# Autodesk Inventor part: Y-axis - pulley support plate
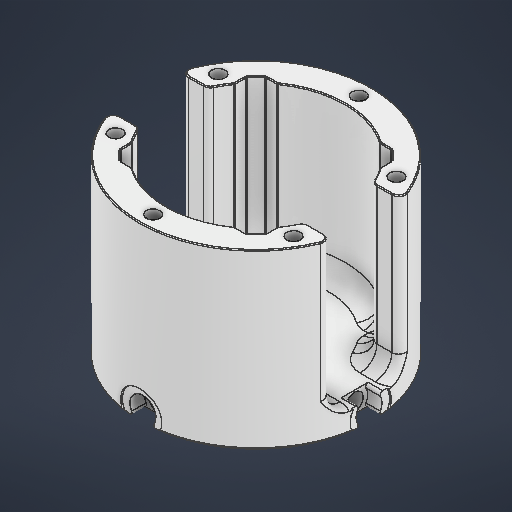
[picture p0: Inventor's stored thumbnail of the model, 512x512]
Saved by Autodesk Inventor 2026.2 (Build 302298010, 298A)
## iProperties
Created: 2026-04
Part Number: Y-axis - pulley support plate
Material: PBT 플라스틱
Document SubType Name: Modeling
Designer: work
Density: 1.31 g/cm^3
Appearance: 매끄러움 - 흰색
Author: work
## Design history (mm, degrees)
sketch "스케치1"
  geometry: L1 (-22, 22)-(22, 22); L2 (22, 22)-(22, -22); L3 (22, -22)-(-22, -22); L4 (-22, -22)-(-22, 22); L5 (-22, 22)-(22, -22); L6 (22, 22)-(-22, -22); L7 (0, 0)-(0, -30); L8 (0, 0)-(25.981, -15); L9 (0, 0)-(25.981, 15); L10 (0, 0)-(0, 30); L11 (0, 0)-(-25.981, 15); L12 (0, 0)-(-25.981, -15); L13 (-32.496, 10)-(32.496, 10); L14 (32.496, 10)-(32.496, -10); L15 (32.496, -10)-(-32.496, -10); L16 (-32.496, -10)-(-32.496, 10); L17 (0, 0)-(34, 0); C1 r 2 at (0, -30); C2 r 2 at (25.981, -15); C3 r 2 at (25.981, 15); C4 r 2 at (0, 30); C5 r 2 at (-25.981, 15); C6 r 2 at (-25.981, -15); C7 r 26 at (0, 0); A1 r 34 centre (0, 0) between (-32.496, 10) and (32.496, -10); 7 further points
  constraints: 34 end point, 10 coincident, 8 centre point, 4 parallel, 3 horizontal, 3 midpoint, 3 point on circle, 3 point on line, 2 perpendicular, 1 vertical, 32 other
  dimensions: "d0" = 44 distance of L2.end L3.end; "d1" = 44 distance of L1.end L2.end; "d2" = 30 distance of L7.start L7.end; "d3" = 4 diameter of C1; "d6" = 360 deg dimension on L7.start L7.end (derived); "d8" = 8 radial gap between concentric circles of A1 C7; "d9" = 4 dimension on C7; "d10" = 20 distance of L13.end L14.end
extrude "돌출1" new body sketch "스케치1" distance "d11" = 45; taper "d12" = 0 deg
sketch "스케치2"
  geometry: L1 (0, 0)-(34, 0); L2 (0, 0)-(24.042, -24.042); L3 (0, 0)-(24.042, 24.042); C1 r 12.75 at (0, 0); A1 r 34 centre (0, 0) between (-32.496, -10) and (32.496, -10) reference; A2 r 34 centre (0, 0) between (32.496, -10) and (34, 0); 2 further points
  constraints: 6 end point, 4 point on circle, 2 centre point, 2 coincident, 1 horizontal, 1 perpendicular
  dimensions: "d13" = 25.5 diameter of C1; "d14" = 45 deg angle of L2 L1
extrude "돌출2" join sketch "스케치2" distance "d15" = 6; taper "d16" = 0 deg
node "작업 평면1"
sketch "스케치3"
  geometry: L1 (-34, -6)-(34, -6) reference; L2 (0, -6)-(0, -3); C1 r 6 at (0, -3); 1 further point
  constraints: 2 end point, 1 centre point, 1 midpoint, 1 vertical
  dimensions: "d20" = 12 diameter of C1; "d33" = 3 distance of L2.start L2.end
extrude "돌출3" cut sketch "스케치3" distance "d18" = 1; taper "d19" = 0 deg
sketch "스케치6"
  geometry: A1 r 6 centre (0, -3) between (5.196, -6) and (-5.196, -6) reference; 2 further points
  constraints: 1 coincident
hole "구멍2" sketch "스케치6" at (0, -3) diameter "d34" = 5; stored, may be unused: countersink angle "d38" = 90 deg, drill point angle "d40" = 0 deg; dims "d35" = 8, "d36" = 7.6, "d37" = 4.2, "d39" = 8
chamfer "모따기1" distance "d45" = 1; stored, may be unused: second distance "d46" = 2, angle "d47" = 45 deg
sketch "스케치7"
  geometry: L1 (-21.25, -21.25)-(21.25, -21.25); L2 (21.25, -21.25)-(21.25, 21.25); L3 (21.25, 21.25)-(-21.25, 21.25); L4 (-21.25, 21.25)-(-21.25, -21.25); L5 (-21.25, -21.25)-(21.25, 21.25); L6 (21.25, -21.25)-(-21.25, 21.25); L7 (-21.25, 18.348)-(-18.348, 21.25); L8 (18.348, -21.25)-(21.25, -18.348); L9 (-18.348, -21.25)-(-21.25, -18.348); L10 (21.25, -18.348)-(18.348, -21.25); L11 (18.348, 21.25)-(21.25, 18.348); 12 further points
  constraints: 22 end point, 4 midpoint, 2 parallel, 2 point on line, 2 symmetric about line, 1 horizontal, 1 perpendicular, 17 other
  dimensions: "d48" = 42.5 distance of L3.end L2.end; "d49" = 42.5 distance of L2.end L1.end; "d50" = 45 deg angle of L3 L7; "d51" = 56 distance of point (19.799, -19.799) point (-19.799, 19.799); "d54" = 360 deg dimension on point (0, 0) L7.start (derived)
extrude "돌출5" cut sketch "스케치7" stored distance "d56" = 10; taper "d57" = 0 deg
node "작업 평면2"
sketch "스케치8"
  geometry: L1 (14.981, -21.25)-(18.348, -21.25) reference; L2 (18.348, -21.25)-(21.25, -18.348) reference; L3 (21.25, -18.348)-(21.25, -14.981) reference; L4 (-32.496, -10)-(-24, -10) reference; L5 (24, -10)-(32.496, -10) reference; L6 (-21.25, -14.981)-(-21.25, -18.348) reference; L7 (-21.25, -18.348)-(-18.348, -21.25) reference; L8 (-18.348, -21.25)-(-14.981, -21.25) reference; L9 (21.25, 14.981)-(21.25, 18.348) reference; L10 (21.25, 18.348)-(18.348, 21.25) reference; L11 (18.348, 21.25)-(14.981, 21.25) reference; L12 (-14.981, 21.25)-(-18.348, 21.25) reference; L13 (-18.348, 21.25)-(-21.25, 18.348) reference; L14 (-21.25, 18.348)-(-21.25, 14.981) reference; L15 (32.496, 10)-(24, 10) reference; L16 (-24, 10)-(-32.496, 10) reference; L17 (14.981, -21.25)-(18.348, -21.25) reference; L18 (18.348, -21.25)-(21.25, -18.348) reference; L19 (21.25, -18.348)-(21.25, -14.981) reference; L20 (24, -10)-(32.496, -10) reference; L21 (-32.496, -10)-(-24, -10) reference; L22 (-21.25, -14.981)-(-21.25, -18.348) reference; L23 (-21.25, -18.348)-(-18.348, -21.25) reference; L24 (-18.348, -21.25)-(-14.981, -21.25) reference; L25 (-21.25, 18.348)-(-21.25, 14.981) reference; L26 (-24, 10)-(-32.496, 10) reference; L27 (32.496, 10)-(24, 10) reference; L28 (21.25, 14.981)-(21.25, 18.348) reference; L29 (21.25, 18.348)-(18.348, 21.25) reference; L30 (18.348, 21.25)-(14.981, 21.25) reference; L31 (-14.981, 21.25)-(-18.348, 21.25) reference; L32 (-18.348, 21.25)-(-21.25, 18.348) reference; C1 r 2 at (25.981, -15) reference; C2 r 2 at (-25.981, -15) reference; C3 r 2 at (0, -30) reference; C4 r 2 at (25.981, 15) reference; C5 r 2 at (0, 30) reference; C6 r 2 at (-25.981, 15) reference; A1 r 26 centre (0, 0) between (21.25, -14.981) and (24, -10) reference; A2 r 34 centre (0, 0) between (-32.496, -10) and (32.496, -10) reference; A3 r 26 centre (0, 0) between (-24, -10) and (-21.25, -14.981) reference; A4 r 26 centre (0, 0) between (-14.981, -21.25) and (14.981, -21.25) reference; A5 r 26 centre (0, 0) between (14.981, 21.25) and (-14.981, 21.25) reference; A6 r 26 centre (0, 0) between (-21.25, 14.981) and (-24, 10) reference; A7 r 34 centre (0, 0) between (-32.496, -10) and (32.496, -10) reference; A8 r 26 centre (0, 0) between (24, 10) and (21.25, 14.981) reference; A9 r 34 centre (0, 0) between (32.496, 10) and (-32.496, 10) reference; A10 r 26 centre (0, 0) between (21.25, -14.981) and (24, -10) reference; A11 r 26 centre (0, 0) between (-24, -10) and (-21.25, -14.981) reference; A12 r 26 centre (0, 0) between (-14.981, -21.25) and (14.981, -21.25) reference; A13 r 26 centre (0, 0) between (-21.25, 14.981) and (-24, 10) reference; A14 r 34 centre (0, 0) between (32.496, 10) and (-32.496, 10) reference; A15 r 26 centre (0, 0) between (24, 10) and (21.25, 14.981) reference; A16 r 26 centre (0, 0) between (14.981, 21.25) and (-14.981, 21.25) reference; 2 further points
extrude "돌출6" join sketch "스케치8" stored distance "d59" = 10; taper "d60" = 0 deg
fillet "모깎기2" dims "d61" = 0.75
fillet "모깎기3" dims "d62" = 2
fillet "모깎기4" dims "d63" = 0.5
fillet "모깎기5" dims "d64" = 4.9
chamfer "모따기2" distance "d65" = 0.25; stored, may be unused: second distance "d66" = 2, angle "d67" = 45 deg
feature "͊耀͌耀͎耀͐耀͒耀͔耀͖耀͘耀" dims "d0" = 44, "d1" = 44, "d2" = 30, "d3" = 4, "d4" = 60, "d6" = 360 deg (derived), "d8" = 8, "d9" = 4, "d10" = 20, "d11" = 45, "d12" = 0, "d13" = 25.5, "d14" = 45 deg, "d15" = 6, "d16" = 0, "d18" = 1, "d19" = 0, "d20" = 12, "d33" = 3, "d34" = 5, "d35" = 8, "d36" = 7.6, "d37" = 4.2, "d38" = 90 deg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
node "솔리드1"
pattern_circular "원형 패턴2" dims "d42" = 360 deg
node "스케치 - 원형 패턴1" dims "d6" = 360 deg (derived)
node "스케치 - 원형 패턴2" dims "d54" = 360 deg (derived)
node "투영된 루프1"
node "투영된 루프2"
feature "A9D066F2-1C7D-4E18-AEED-F7BC21143FA4" dims "d34" = 5, "d35" = 8, "d36" = 7.6, "d37" = 4.2, "d38" = 90 deg, "d39" = 8, "d40" = 0
